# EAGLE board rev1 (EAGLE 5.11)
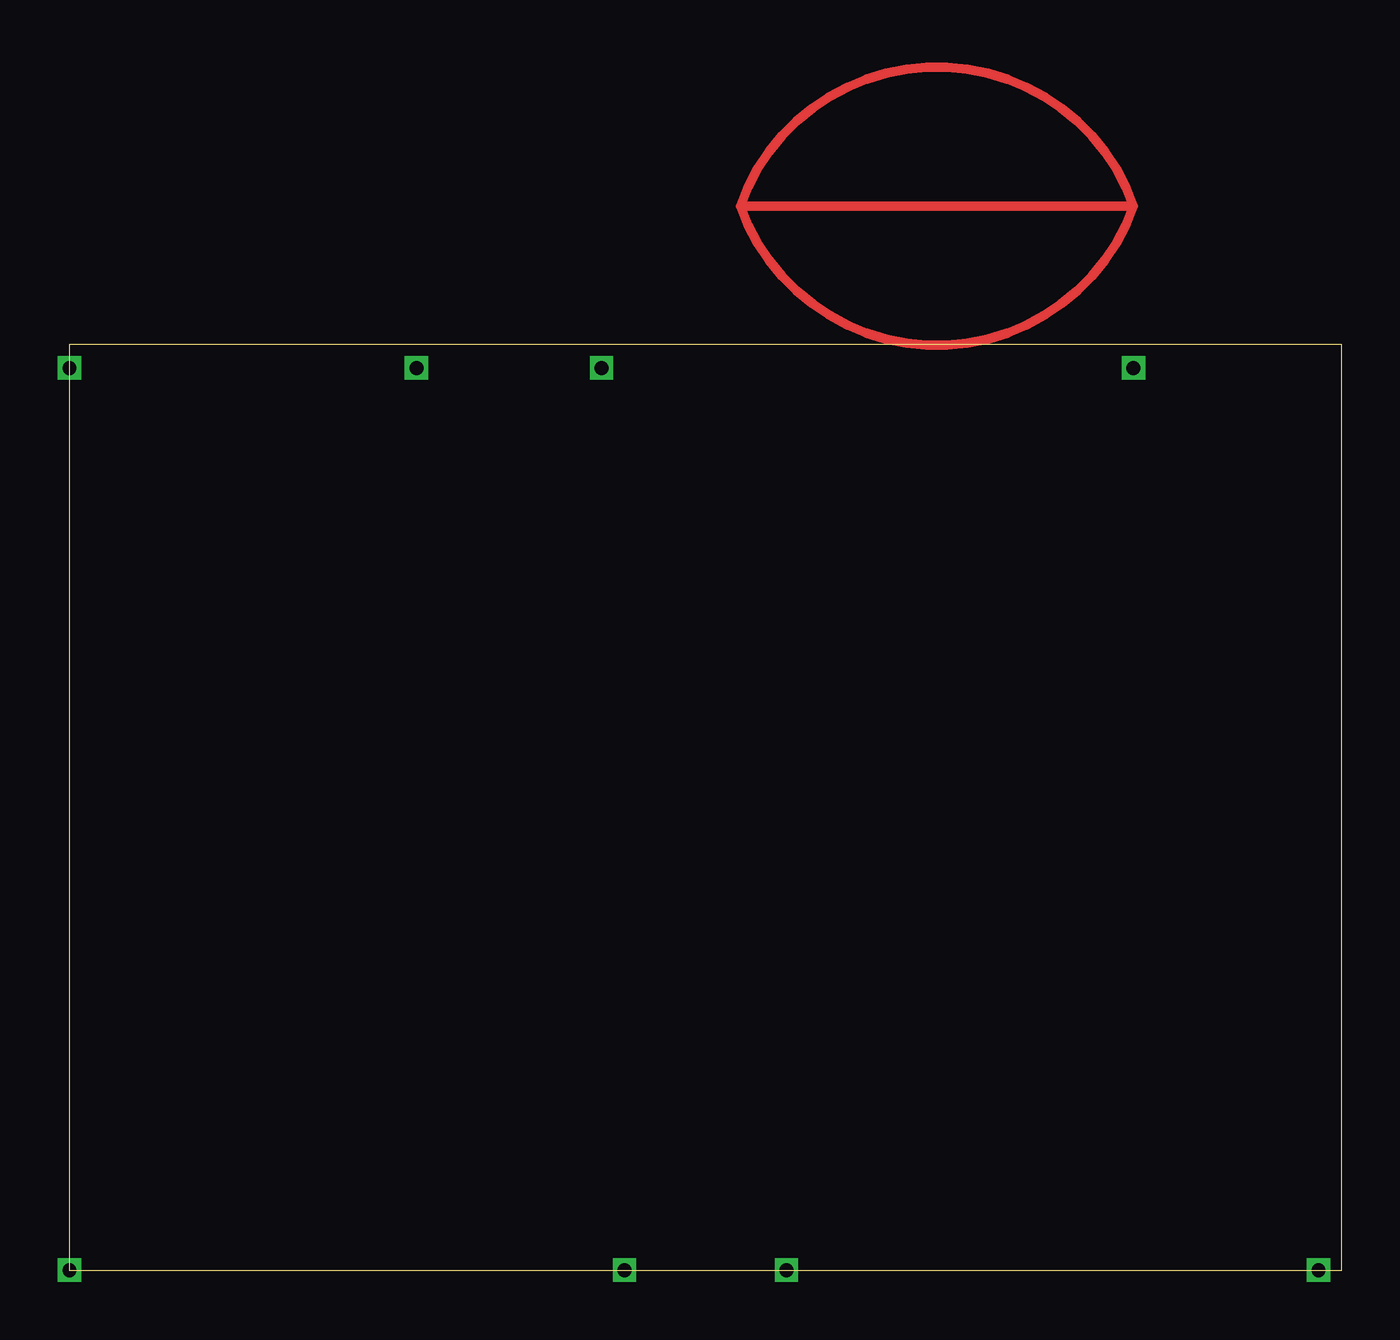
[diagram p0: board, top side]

Size 55 x 40 mm. Coordinates in mm from the lower left corner, seen from the top.
Outline: 0,0 55,0 55,40 0,40 0,0
Copper layers (1*16): Top 0.035mm / dielectric 1.5mm / Bottom 0.035mm
Design rules "default": minimum track width 10mil, minimum drill 0.6mm, track to track 8mil, track to pad 8mil, pad to pad 8mil, via to via 8mil, smd to smd 8mil, copper to edge 40mil, drill to drill 8mil, minimum pad ring 10mil, minimum via ring 8mil, stop-mask expansion 4mil, vias tented up to drill 0mil, thermal gap 10mil

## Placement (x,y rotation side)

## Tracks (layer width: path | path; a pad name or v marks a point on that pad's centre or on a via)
N$1  (via drill 0.6)
  other vias: 0,0
N$2  (via drill 0.6)
  other vias: 24,0
N$3  (via drill 0.6)
  other vias: 31,0
N$4  (via drill 0.6)
  other vias: 54,0
N$5  (via drill 0.6)
  other vias: 0,39
N$6  (via drill 0.6)
  other vias: 46,39
N$7  (via drill 0.6)
  other vias: 23,39
N$8  (via drill 0.6)
  other vias: 15,39
N$11
  Top 0.406: 46,46 arc-141 29,46 | 29,46 arc-141 46,46 | 29,46 46,46

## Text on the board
Document: 1mm=1ft | existing | raspberry | raspberry | xplanted '11 | yel del | tartarian | burbank | cherry | 15 | plum | 12 | 12 | bartlett | pear | staymans | 15 | stella | santa rosa | winesap | cherry | plum | 8 | honey | crisp | 12 | 12 | 6 | red haven | peach | seckel | veteran | 15 | white | white | pear | peach | peach | peach | 15 | 10 | 10 | 10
